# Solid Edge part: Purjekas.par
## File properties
Author: Administrator
Template: Normal.par
Last saved by: Administrator
Revision: 28
Application: Solid Edge
Accuracy: 0,990
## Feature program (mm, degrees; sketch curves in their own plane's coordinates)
make body feature "unnamed MakeBodyFeature 1"
body pattern "unnamed BodyPattern 1"
pattern "unnamed Pattern 1"
fillet "Round_2" radius 15
sketch for "ExtrudedProtrusion_2" plane through (0, 0, 0) normal (0, 0, 1) x-axis (1, 0, 0)
  line (-185, -2.5) -> (-35, -2.5)
  line (-35, 2.5) -> (-35, -2.5)
  line (-185, 2.5) -> (-35, 2.5)
  line (-185, -2.5) -> (-185, 2.5)
extrude "ExtrudedProtrusion_2" add finite 275 along -normal
sketch for "ExtrudedCutout_2" plane through (0, 0, 0) normal (0, -1, 0) x-axis (1, 0, 0)
  arc centre (53.634, -140) radius 238.634 from (-185, -140) to (-143.7187, -274.157) ccw
  arc centre (-177.9237, -135.3074) radius 143.0007 from (-143.7187, -274.157) to (-35, -140) ccw
  line (-35, -140) -> (-30, -140)
  line (-30, -140) -> (-30, -280)
  line (-30, -280) -> (-190, -280)
  line (-190, -280) -> (-190, -140)
  line (-185, -140) -> (-190, -140)
extrude "ExtrudedCutout_2" cut finite 5 symmetric
fillet "Round_3" radius 2.45
thinwall "Thinwall_1"  Thickness = 5 mm
fillet "Round_5" radius 1.5
logasc func "Lip_Groove_9"  LipOrGrooveWidth = 2 mm; LipOrGrooveHeight = 5 mm
sketch for "ExtrudedCutout_4" plane through (0, 0, 0) normal (0, 0, 1) x-axis (1, 0, 0)
  line (317.1058, 0.75) -> (319.6058, 0.75)
  line (319.6058, 0.75) -> (319.6058, -0.75)
  line (319.6058, -0.75) -> (317.1058, -0.75)
  line (317.1058, -0.75) -> (317.1058, 0.75)
extrude "ExtrudedCutout_4" cut finite 2 along -normal
web network "WebNetwork_2"  Thickness = 2.5 mm
sketch used by "ExtrudedCutout_5" plane through (-32.8942, -0.0002, -62.6023) normal (-1, 0, 0) x-axis (0, -1, 0)
extrude "ExtrudedCutout_5" cut finite 0.1 along -normal
web network "WebNetwork_4"  Thickness = 2.5 mm
sketch for "unnamed Cutout 1" plane through (-32.8942, -0.0002, -44.375) normal (-1, 0, 0) x-axis (0, -1, 0)
  line (5.0002, -21.3077) -> (5.0002, -22.5577)
  line (5.0002, -22.5577) -> (-4.9998, -22.5577)
  line (-4.9998, -22.5577) -> (-4.9998, -21.3077)
  line (-4.9998, -21.3077) -> (5.0002, -21.3077)
extrude "unnamed Cutout 1" cut through along -normal
sketch for "unnamed Protrusion 1" plane through (-167.9145, 6.1428, -91.25) normal (0, 0, -1) x-axis (0, 1, 0)
  circle centre (-6.1428, 60.0203) radius 10
extrude "unnamed Protrusion 1" add through along +normal
sketch for "ExtrudedProtrusion_5" plane through (-167.9145, 6.1428, -91.25) normal (0, 0, -1) x-axis (0, 1, 0)
extrude "ExtrudedProtrusion_5" add finite 22.5 along -normal
sketch used by "ExtrudedCutout_7" plane through (-107.8942, 0, -68.75) normal (0, 0, 1) x-axis (0, 1, 0)
  line (-5.6162, 0) -> (6.6778, 0)
  line (0.05, -2.7567) -> (0.05, 4.2977)
  circle centre (0.05, 0) radius 5
extrude "ExtrudedCutout_7" cut finite 50 along -normal
fillet "Round_6" radius 5
sketch used by "ExtrudedCutout_8" plane through (-30.3942, -0.0002, -62.4423) normal (1, 0, 0) x-axis (0, 1, 0)
extrude "ExtrudedCutout_8" cut finite 0.1 along -normal
web network "WebNetwork_7"  Thickness = 2.5 mm
sketch used by "unnamed Protrusion 2" plane through (0, 0, 0) normal (0, -1, 0) x-axis (1, 0, 0)
extrude "unnamed Protrusion 2" add through along +normal
sketch used by "unnamed Cutout 2" plane through (92.1058, 0, -47.7619) normal (0, 0, 1) x-axis (0, 1, 0)
extrude "unnamed Cutout 2" cut through along -normal
sketch for "unnamed Protrusion 3" #1 plane through (51.2587, 0, -83.75) normal (0, 0, 1) x-axis (0, 1, 0)
  circle centre (40, 74.4948) radius 2.5
sketch for "unnamed Protrusion 3" #2 plane through (51.2587, 0, -83.75) normal (0, 0, 1) x-axis (0, 1, 0)
  circle centre (-40, 74.4948) radius 2.5
sketch for "unnamed Protrusion 3" #3 plane through (51.2587, 0, -83.75) normal (0, 0, 1) x-axis (0, 1, 0)
  circle centre (0, -48.2703) radius 2.5
extrude "unnamed Protrusion 3" add through along +normal
fillet "Round_7" radius 2
sketch for "unnamed Protrusion 4" plane through (0, 0, 0) normal (0, -1, 0) x-axis (1, 0, 0)
  line (-345, -60) -> (-95, -60)
  line (-95, -60) -> (-95, -65)
  line (-345, -65) -> (-95, -65)
  line (-345, -60) -> (-345, -65)
extrude "unnamed Protrusion 4" add through along +normal
sketch for "unnamed Cutout 3" plane through (-220.6473, 0, -60) normal (0, 0, 1) x-axis (0, 1, 0)
  bspline degree 3 poles (17.2223, 54.5212) (18.3044, 52.6883) (19.3003, 50.7444) (21.2732, 46.39) (22.2232, 43.9745) (23.5501, 40.182) (23.9738, 38.896) (24.7893, 36.2806) (25.1808, 34.9517) (26.3052, 30.9333) (26.9879, 28.2148) (28.2521, 22.7003) (28.8306, 19.9166) (29.9026, 14.2962) (30.3947, 11.4667) (31.7624, 2.9189) (32.5265, -2.8324) (33.8323, -14.4302) (34.3714, -20.2601) (35.2605, -31.9787) (35.6096, -37.859) (36.1377, -49.6596) (36.3163, -55.5779) (36.5129, -67.4342) (36.5307, -73.3589) (36.3527, -91.125) (35.9268, -102.9485) (35.2004, -114.7526) (34.9767, -118.3864) (34.7246, -122.0179) (34.4439, -125.6473) knots 0 0.0415 0.0878 0.1109 0.1341 0.1804 0.2267 0.2729 0.3655 0.4581 0.5507 0.6433 0.7359 0.921 1 multiplicities 4 2 2 2 2 2 2 2 2 2 2 2 2 3 4
  line (-34.444, -125.6473) -> (34.4439, -125.6473)
  bspline degree 3 poles (-34.444, -125.6473) (-34.7274, -121.9825) (-34.9818, -118.3146) (-35.2071, -114.6436) (-35.5705, -108.7233) (-35.8583, -102.7925) (-36.2809, -90.9308) (-36.4159, -85.0012) (-36.5886, -67.2128) (-36.3974, -55.3699) (-35.5973, -37.6305) (-35.2446, -31.7308) (-34.3465, -19.9728) (-33.802, -14.1209) (-32.8117, -5.3868) (-32.4529, -2.486) (-31.6695, 3.295) (-31.2455, 6.1715) (-30.3233, 11.8873) (-29.8257, 14.7234) (-28.7427, 20.3497) (-28.1587, 23.1328) (-26.8847, 28.6355) (-26.1956, 31.3505) (-24.6959, 36.6558) (-23.8892, 39.2344) (-22.1258, 44.2287) (-21.179, 46.616) (-19.622, 50.0238) (-19.0816, 51.1278) (-18.232, 52.7388) (-17.9433, 53.2666) (-17.5091, 54.0302) (-17.3683, 54.2733) (-17.2261, 54.5144) knots 0 0.0794 0.1721 0.2648 0.4501 0.5428 0.6354 0.6818 0.7281 0.7744 0.8208 0.8671 0.9134 0.9598 0.983 0.9945 1 multiplicities 4 3 2 2 2 2 2 2 2 2 2 2 2 2 2 2 4
  arc centre (0.0001, 44.3528) radius 20 from (-17.2261, 54.5144) to (17.2223, 54.5212) cw
extrude "unnamed Cutout 3" cut through along -normal
sketch for "ExtrudedProtrusion_10" #1 plane through (-170.0129, 6.7777, -88.75) normal (0, 0, 1) x-axis (0, 1, 0)
  circle centre (28.2223, 84.9872) radius 2.5
sketch for "ExtrudedProtrusion_10" #2 plane through (-170.0129, 6.7777, -88.75) normal (0, 0, 1) x-axis (0, 1, 0)
  circle centre (-41.7777, 84.9872) radius 2.5
sketch for "ExtrudedProtrusion_10" #3 plane through (-170.0129, 6.7777, -88.75) normal (0, 0, 1) x-axis (0, 1, 0)
  circle centre (35.7223, -65.0128) radius 2.5
sketch for "ExtrudedProtrusion_10" #4 plane through (-170.0129, 6.7777, -88.75) normal (0, 0, 1) x-axis (0, 1, 0)
  circle centre (-49.2777, -65.0128) radius 2.5
extrude "ExtrudedProtrusion_10" add finite 25 along +normal
fillet "Round_10" radius 4
fillet "Round_11" radius 0.95
sketch used by "ExtrudedProtrusion_11" plane through (-350, -0.0416, -33.4206) normal (-1, 0, 0) x-axis (0, -1, 0)
extrude "ExtrudedProtrusion_11" add finite 10 along +normal
sketch used by "ExtrudedCutout_13" plane through (-355, 0, -1.5) normal (0, 0, 1) x-axis (0, -1, 0)
extrude "ExtrudedCutout_13" cut finite 65 along -normal
sketch for "ExtrudedCutout_14" plane through (-355, 0, -1.5) normal (0, 0, 1) x-axis (0, -1, 0)
extrude "ExtrudedCutout_14" cut finite 65 along -normal
fillet "Round_12" radius 1
sketch used by "ExtrudedProtrusion_12" plane through (0, 0, 0) normal (0, 0, 1) x-axis (1, 0, 0)
extrude "ExtrudedProtrusion_12" add finite 100 along -normal
sketch used by "ExtrudedProtrusion_13" plane through (0, 0, -100) normal (0, 0, 1) x-axis (1, 0, 0)
extrude "ExtrudedProtrusion_13" add finite 75 along -normal
sketch used by "unnamed Cutout 4" plane through (-387.5, -2.75, -137.5) normal (0, -1, 0) x-axis (1, 0, 0)
extrude "unnamed Cutout 4" cut through along -normal
fillet "Round_13" radius 2.5
swept protrusion "unnamed SweptProtrusion 1"
fillet "Round_14" radius 2.5
sketch for "ExtrudedProtrusion_14" plane through (0, 0, 0) normal (0, 0, 1) x-axis (1, 0, 0)
  line (-345.75, -49) -> (-345.75, -36)
  arc centre (-344.75, -36) radius 1 from (-345.75, -36) to (-344.75, -35) cw
  line (-344.75, -35) -> (-343.75, -35)
  arc centre (-343.75, -36) radius 1 from (-343.75, -35) to (-342.75, -36) cw
  line (-342.75, -36) -> (-342.75, -49)
  arc centre (-343.75, -49) radius 1 from (-343.75, -50) to (-342.75, -49) ccw
  line (-343.75, -50) -> (-344.75, -50)
  arc centre (-344.75, -49) radius 1 from (-345.75, -49) to (-344.75, -50) ccw
extrude "ExtrudedProtrusion_14" add finite 10 along +normal
sketch for "unnamed Cutout 5" #1 plane through (-342.75, -42.5, 5) normal (1, 0, 0) x-axis (0, 1, 0)
sketch for "unnamed Cutout 5" #2 plane through (-342.75, -42.5, 5) normal (1, 0, 0) x-axis (0, 1, 0)
  line (-7.5, 2.5) -> (-2.5, 2.5)
  arc centre (-2.5, 1.5) radius 1 from (-2.5, 2.5) to (-1.5, 1.5) cw
  line (-1.5, 1.5) -> (-1.5, -2)
  arc centre (-2.5, -2) radius 1 from (-2.5, -3) to (-1.5, -2) ccw
  line (-7.5, -3) -> (-2.5, -3)
  line (-7.5, 2.5) -> (-7.5, -3)
extrude "unnamed Cutout 5" cut through along -normal
fillet "Round_16" radius 1
pattern "Pattern_2" of "Round_16", "ExtrudedProtrusion_14", "unnamed Cutout 5" along a curve  XDirCount = 2; XDirSpacing = 90 mm
extrude "unnamed Protrusion 5" add finite 10
extrude "unnamed Cutout 6" cut through
fillet "unnamed Round 1"
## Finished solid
Body 1: solid body, 356 faces, 805 edges, 451 vertices, 2 internal voids.
  Faces by surface: cylinder 139, plane 95, torus 42, sphere 41, blend 19, offset 12, spline 4, swept 4
  Edges by curve: line 341, circle 326, intersection 126, curve on surface 10, spline 2
Body 2: solid body, 4 faces, 7 edges, 5 vertices.
  Faces by surface: plane 3, spline 1
  Edges by curve: curve on surface 4, line 3
Bounding box of the edges (mm; curved faces can reach further): 774.967 x 204.452 x 286.657, from (-424.9667, -101.662, -274.157) to (350, 102.7905, 12.5).
Cylindrical faces by radius (mm): R0.95 x2, R1 x96, R1.5 x1, R2 x1, R2.45 x2, R2.5 x25, R4 x2, R4.5 x2, R5 x1, R10 x2, R20 x1, R68.1866 x1, R96.4307 x1, R143.0007 x1, R238.634 x1
Toroidal faces (ring radius, tube radius in mm): R2 r1 x24, R3.5 r1 x4, R4.5 r2 x2, R5 r5 x1, R10 r2.5 x1, R20.95 r0.95 x1, R24 r4 x1, R65.6866 r2.5 x2, R93.9307 r2.5 x2, R140.5507 r2.45 x2, R236.184 r2.45 x2
Spherical faces by radius (mm): R1 x32, R2.5 x9
Planar faces by outward normal: +x 16, +y 16, +z 20, -x 15, -y 17, -z 14
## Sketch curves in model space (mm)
line (-342.75, -35, 7.5) -> (-342.75, -35, 2)
line (-342.75, -40, 7.5) -> (-342.75, -35, 7.5)
arc centre (-342.75, -40, 6.5) radius 1 from (-342.75, -41, 6.5) through (-342.75, -40.6862, 7.2274) to (-342.75, -40, 7.5)
line (-342.75, -41, 6.5) -> (-342.75, -41, 3)
arc centre (-342.75, -40, 3) radius 1 from (-342.75, -41, 3) through (-342.75, -40.6862, 2.2726) to (-342.75, -40, 2)
line (-342.75, -40, 2) -> (-342.75, -35, 2)
arc centre (-342.75, -45, 6.5) radius 1 from (-342.75, -45, 7.5) through (-342.75, -44.2726, 7.1862) to (-342.75, -44, 6.5)
line (-342.75, -44, 6.5) -> (-342.75, -44, 3)
arc centre (-342.75, -45, 3) radius 1 from (-342.75, -45, 2) through (-342.75, -44.2726, 2.3138) to (-342.75, -44, 3)
line (-342.75, -50, 2) -> (-342.75, -45, 2)
line (-342.75, -50, 7.5) -> (-342.75, -50, 2)
line (-342.75, -50, 7.5) -> (-342.75, -45, 7.5)
circle centre (-105, 42.5, -88.75) radius 2.5
circle centre (-105, -42.5, -88.75) radius 2.5
circle centre (-255, 35, -88.75) radius 2.5
circle centre (-255, -35, -88.75) radius 2.5
line (-255, -68.873, -88.75) -> (-255, 55.0295, -88.75)
line (-105, -82.2981, -88.75) -> (-105, 76.2859, -88.75)
line (-258.2622, -35, -88.75) -> (-235.3276, -35, -88.75)
line (-258.2622, 35, -88.75) -> (-242.8793, 35, -88.75)
line (-98.5594, -42.5, -88.75) -> (-123.1721, -42.5, -88.75)
line (-98.5594, 42.5, -88.75) -> (-120.3752, 42.5, -88.75)
circle centre (-355.5, 0, -1.5) radius 2.5
line (-360.5, -7.5, -1.5) -> (-351.5, -7.5, -1.5)
line (-360.5, 7.5, -1.5) -> (-360.5, -7.5, -1.5)
line (-351.5, 7.5, -1.5) -> (-360.5, 7.5, -1.5)
line (-351.5, 7.5, -1.5) -> (-351.5, 4.5, -1.5)
line (-351.5, 4.5, -1.5) -> (-355.5, 4.5, -1.5)
arc centre (-355.5, 0, -1.5) radius 4.5 from (-355.5, -4.5, -1.5) through (-359.998, 0.1333, -1.5) to (-355.5, 4.5, -1.5)
line (-351.5, -4.5, -1.5) -> (-355.5, -4.5, -1.5)
line (-351.5, -4.5, -1.5) -> (-351.5, -7.5, -1.5)
arc centre (-265.0001, 0.0001, -60) radius 20 from (-275.1617, -17.2261, -60) through (-284.9914, 0.589, -60) to (-275.1685, 17.2223, -60)
spline (-275.1685, 17.2223, -60) -> (-186.5618, 35.3617, -60) -> (-95, 34.4439, -60)
line (-95, -34.4439, -60) -> (-95, 34.4439, -60)
spline (-95, -34.4439, -60) -> (-186.6436, -35.3567, -60) -> (-275.1617, -17.2261, -60)
line (-350, -7.5, -1.5) -> (-350, -7.5, -6.5)
line (-350, -7.5, -6.5) -> (-350, 7.5, -6.5)
line (-350, 7.5, -6.5) -> (-350, 7.5, -1.5)
line (-350, 7.5, -1.5) -> (-350, -7.5, -1.5)
line (-350, -7.5, -56.5) -> (-350, -7.5, -61.5)
line (-350, -7.5, -61.5) -> (-350, 7.5, -61.5)
line (-350, 7.5, -61.5) -> (-350, 7.5, -56.5)
line (-350, 7.5, -56.5) -> (-350, -7.5, -56.5)
circle centre (-355.5, 0, 0) radius 2.5
line (-248.8639, 0, 0) -> (-427.5047, 0, 0)
line (-344.25, 50, 0) -> (-344.25, -50, 0)
arc centre (-343.75, -36, 0) radius 1 from (-343.75, -35, 0) through (-343.0226, -35.3138, 0) to (-342.75, -36, 0)
line (-342.75, -36, 0) -> (-342.75, -49, 0)
arc centre (-343.75, -49, 0) radius 1 from (-343.75, -50, 0) through (-343.0226, -49.6862, 0) to (-342.75, -49, 0)
line (-343.75, -50, 0) -> (-344.75, -50, 0)
arc centre (-344.75, -49, 0) radius 1 from (-345.75, -49, 0) through (-345.4362, -49.7274, 0) to (-344.75, -50, 0)
line (-345.75, -49, 0) -> (-345.75, -36, 0)
arc centre (-344.75, -36, 0) radius 1 from (-345.75, -36, 0) through (-345.4362, -35.2726, 0) to (-344.75, -35, 0)
line (-344.75, -35, 0) -> (-343.75, -35, 0)
line (-364.1498, 0, -100) -> (-398.159, 0, -100)
line (-425, -2.75, -100) -> (-350, -2.75, -100)
line (-425, 2.75, -100) -> (-425, -2.75, -100)
line (-425, 2.75, -100) -> (-350, 2.75, -100)
line (-350, 2.75, -100) -> (-350, -2.75, -100)
arc centre (-338.5, 56.0215, 0) radius 5 from (-343.5, 56.0215, 0) through (-342.3531, 59.208, 0) to (-339.7197, 60.8705, 0)
spline (324.6058, 0, 0) -> (165.0729, 57.0892, 0) -> (-339.7197, 60.8705, 0)
spline (-339.7197, -60.8705, 0) -> (181.9734, -51.803, 0) -> (324.6058, 0, 0)
arc centre (-338.5, -56.0215, 0) radius 5 from (-343.5, -56.0215, 0) through (-342.3531, -59.208, 0) to (-339.7197, -60.8705, 0)
line (-343.5, -56.0215, 0) -> (-343.5, 56.0215, 0)
line (319.6058, 0.75, 0) -> (319.6058, -0.75, 0)
line (319.6058, -0.75, 0) -> (317.1058, -0.75, 0)
line (317.1058, -0.75, 0) -> (317.1058, 0.75, 0)
line (317.1058, 0.75, 0) -> (319.6058, 0.75, 0)
line (-32.8942, 11.1809, -90) -> (-32.8942, -12.0861, -90)
line (-32.8942, -2.5, -90) -> (-32.8942, -2.5, -85)
line (-32.8942, -2.5, -85) -> (-32.8942, 2.5, -85)
line (-32.8942, 2.5, -85) -> (-32.8942, 2.5, -90)
line (-32.8942, 2.5, -90) -> (-32.8942, -2.5, -90)
line (-31.6442, 47.593, 0) -> (-31.6442, -7.0445, 0)
circle centre (-107.8942, 0, -91.25) radius 10
circle centre (-107.8942, 0.05, -68.75) radius 5
line (-107.8942, -5.6162, -68.75) -> (-107.8942, 6.6778, -68.75)
line (-105.1374, 0.05, -68.75) -> (-112.1919, 0.05, -68.75)
line (214.6058, 0, -50.2619) -> (214.6058, 0, -47.7619)
line (214.6058, 0, -47.7619) -> (-30.3942, 0, -47.7619)
line (-30.3942, 0, -47.7619) -> (-30.3942, 0, -50.2619)
line (-30.3942, 0, -50.2619) -> (214.6058, 0, -50.2619)
line (-32.8942, -25, 0) -> (-32.8942, -25, -83.75)
line (-32.8942, -25, -83.75) -> (-32.8942, 25, -83.75)
line (-32.8942, 25, -83.75) -> (-32.8942, 25, 0)
line (-32.8942, 25, 0) -> (-32.8942, -25, 0)
line (-30.3942, -14.2583, -85) -> (-30.3942, 13.1082, -85)
line (-30.3942, 5, -83.75) -> (-30.3942, 5, -85)
line (-30.3942, 5, -85) -> (-30.3942, -5, -85)
line (-30.3942, -5, -85) -> (-30.3942, -5, -83.75)
line (-30.3942, -5, -83.75) -> (-30.3942, 5, -83.75)
line (-389.1818, -2.75, -175) -> (-368.1088, -2.75, -175)
arc centre (-418.1646, -2.75, -128.6984) radius 68.1866 from (-368.1088, -2.75, -175) through (-354.9935, -2.75, -154.3662) to (-350, -2.75, -130.4324)
line (-350, -2.75, -130.4324) -> (-350, -2.75, -178.4013)
line (-425, -2.75, -178.4013) -> (-350, -2.75, -178.4013)
line (-425, -2.75, -100) -> (-425, -2.75, -178.4013)
arc centre (-328.5693, -2.75, -100) radius 96.4307 from (-425, -2.75, -100) through (-415.5859, -2.75, -141.557) to (-389.1818, -2.75, -175)
line (-110, 37.9457, 0) -> (-110, -54.2675, 0)
line (-185, -2.5, 0) -> (-35, -2.5, 0)
line (-185, -2.5, 0) -> (-185, 2.5, 0)
line (-185, 2.5, 0) -> (-35, 2.5, 0)
line (-35, 2.5, 0) -> (-35, -2.5, 0)
line (-30.3942, -35.2931, -47.7619) -> (-30.3942, 35.2931, -47.7619)
spline (-30.3942, 35.2931, -47.7619) -> (11.853, 27.0288, -47.7619) -> (87.9382, 5.1738, -47.7619)
arc centre (87.1058, 2.8164, -47.7619) radius 2.5 from (89.6058, 2.8164, -47.7619) through (89.1036, 4.3194, -47.7619) to (87.9382, 5.1738, -47.7619)
line (89.6058, -2.8164, -47.7619) -> (89.6058, 2.8164, -47.7619)
arc centre (87.1058, -2.8164, -47.7619) radius 2.5 from (87.9382, -5.1738, -47.7619) through (89.1882, -4.1997, -47.7619) to (89.6058, -2.8164, -47.7619)
spline (87.9382, -5.1738, -47.7619) -> (11.8419, -27.0313, -47.7619) -> (-30.3942, -35.2931, -47.7619)
arc centre (-350, -3.6163, -6.1992) radius 68.8958 from (-350, 0, -75) through (-350, 49.7681, -49.7506) to (-350, 65, 0)
line (-350, 0, 0) -> (-350, 0, -75)
line (-350, 0, 0) -> (-350, 65, 0)
line (-35, 0, -140) -> (-30, 0, -140)
line (-30, 0, -140) -> (-30, 0, -280)
line (-30, 0, -280) -> (-190, 0, -280)
line (-190, 0, -280) -> (-190, 0, -140)
line (-185, 0, -140) -> (-190, 0, -140)
arc centre (53.634, 0, -140) radius 238.634 from (-185, 0, -140) through (-174.4463, 0, -210.1824) to (-143.7187, 0, -274.157)
arc centre (-177.9237, 0, -135.3074) radius 143.0007 from (-143.7187, 0, -274.157) through (-66.8239, 0, -225.3409) to (-35, 0, -140)
line (-350, 0, 0) -> (-350, 80.0052, 0)
line (-350, 0, 0) -> (-350, 0, -105.1364)
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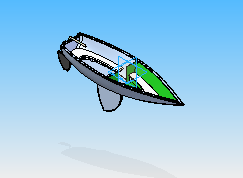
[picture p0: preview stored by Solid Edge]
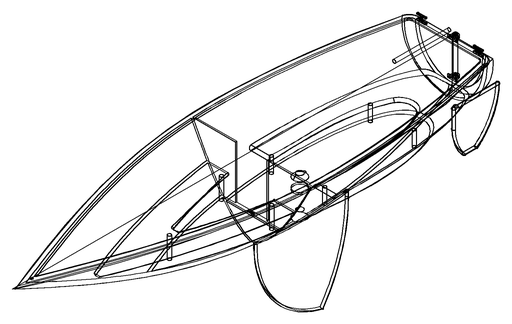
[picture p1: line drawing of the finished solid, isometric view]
